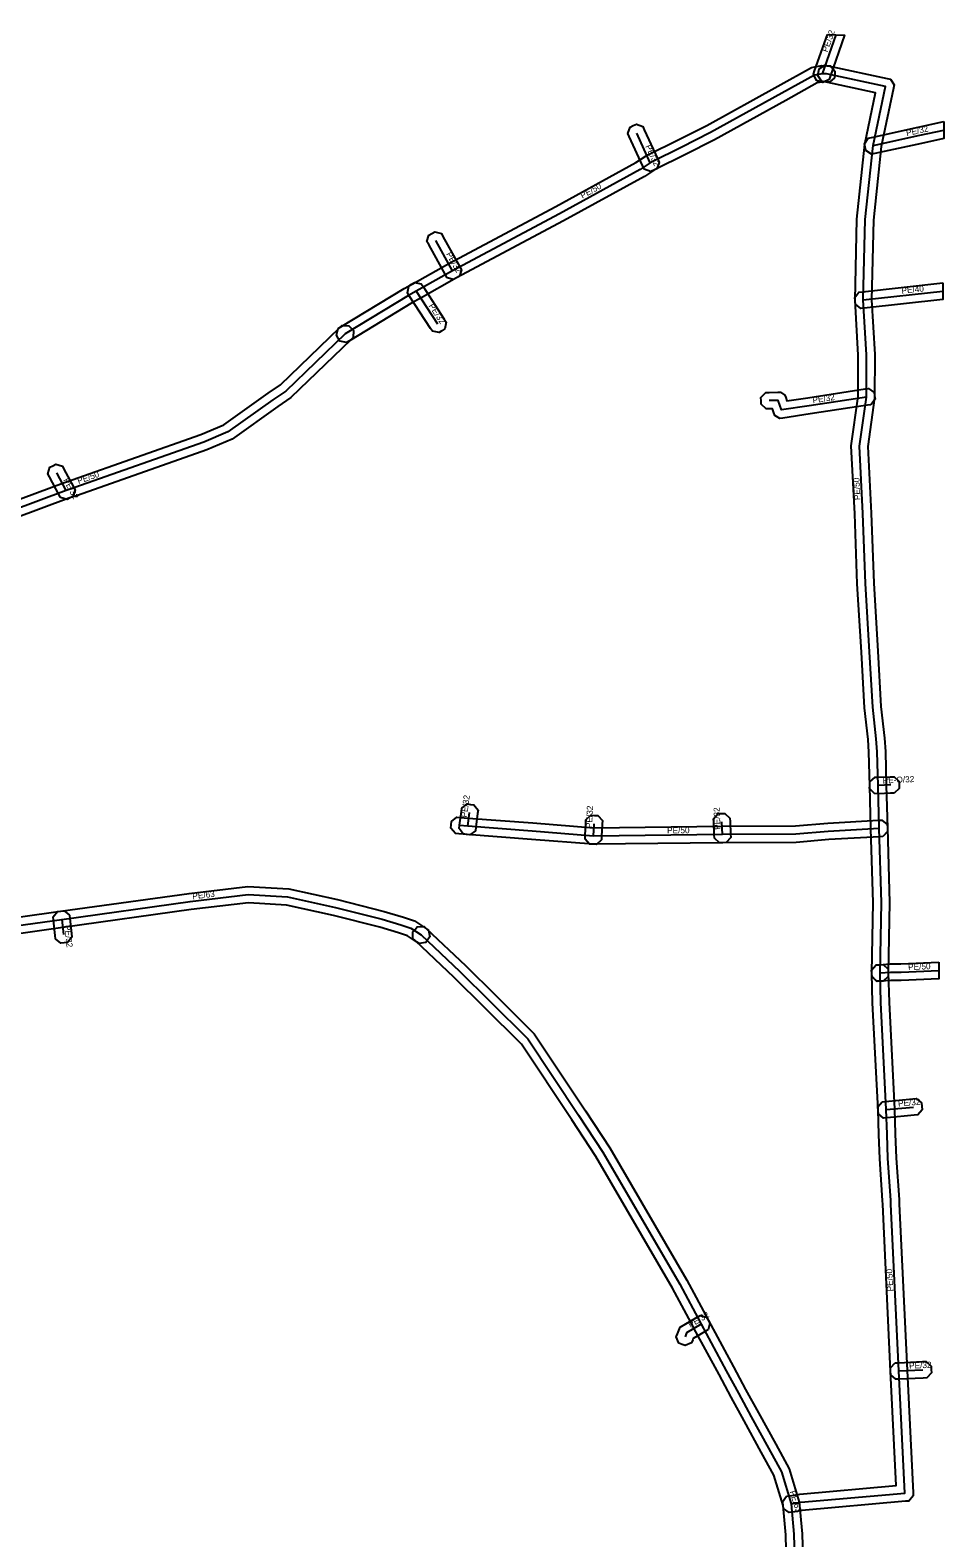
# Model space of a CAD drawing. Extents: x -682697 to -681888, y -1059966 to -1059631.
# Drawn here: x -681998.6 to -681887.6, y -1059827 to -1059643.6 of the extents above; entities that cross this region are included whole.
import ezdxf

# ---------------------------------------------------------------- set-up
doc = ezdxf.new("R2010")
doc.units = 0
for name, color, linetype in [('1', 7, 'Continuous'), ('24', 7, 'Continuous'), ('30', 7, 'Continuous')]:
    doc.layers.add(name, color=color, linetype=linetype)

msp = doc.modelspace()

# ---------------------------------------------------------------- linework, layer by layer
at = {"layer": '1'}
for points in [[(-681901.72, -1059644.16), (-681899.63, -1059644.25), (-681901.39, -1059649.25), (-681901.52, -1059649.64), (-681902.27, -1059650), (-681902.66, -1059649.86), (-681903.05, -1059649.73), (-681903.41, -1059648.98), (-681903.27, -1059648.59)], [(-681901.48, -1059649.97), (-681901.89, -1059649.95), (-681902.27, -1059649.93), (-681902.95, -1059650.05), (-681906.79, -1059652.17), (-681915.45, -1059656.97), (-681919.06, -1059658.79), (-681922.58, -1059660.53), (-681922.74, -1059660.61), (-681923.96, -1059661.44), (-681933.8, -1059666.83), (-681946.8, -1059673.76), (-681951.22, -1059676.24), (-681952.15, -1059676.76), (-681959.82, -1059681.42), (-681960.18, -1059681.63), (-681960.98, -1059681.43), (-681961.2, -1059681.08), (-681961.41, -1059680.72), (-681961.21, -1059679.92), (-681960.86, -1059679.71), (-681953.16, -1059675.04), (-681952.2, -1059674.5), (-681947.76, -1059672), (-681934.74, -1059665.07), (-681925, -1059659.74), (-681923.76, -1059658.89), (-681923.47, -1059658.74), (-681919.96, -1059657.01), (-681916.39, -1059655.21), (-681907.75, -1059650.42), (-681903.63, -1059648.15), (-681902.39, -1059647.91), (-681901.77, -1059647.95), (-681901.36, -1059647.98), (-681900.81, -1059648.6), (-681900.83, -1059649.01), (-681900.86, -1059649.42)], [(-681896.33, -1059758.67), (-681896.32, -1059758.26), (-681896.15, -1059749.72), (-681896.43, -1059740.74), (-681896.56, -1059735.51), (-681896.66, -1059731.44), (-681896.78, -1059729.9), (-681897.21, -1059726.04), (-681897.59, -1059719.28), (-681898.08, -1059710.97), (-681898.4, -1059702.43), (-681898.82, -1059694.19), (-681897.98, -1059688.18), (-681897.97, -1059683.15), (-681898.36, -1059676.45), (-681898.12, -1059666.6), (-681897.15, -1059657.49), (-681895.85, -1059651.24), (-681902.04, -1059649.93), (-681902.44, -1059649.84), (-681902.89, -1059649.15), (-681902.81, -1059648.74), (-681902.72, -1059648.34), (-681902.03, -1059647.89), (-681901.62, -1059647.97), (-681894.46, -1059649.49), (-681894.06, -1059649.58), (-681893.61, -1059650.27), (-681893.69, -1059650.67), (-681895.17, -1059657.79), (-681896.12, -1059666.74), (-681896.36, -1059676.41), (-681895.97, -1059683.09), (-681895.98, -1059688.32), (-681896.82, -1059694.27), (-681896.4, -1059702.35), (-681896.08, -1059710.87), (-681895.59, -1059719.16), (-681895.21, -1059725.88), (-681894.78, -1059729.72), (-681894.66, -1059731.34), (-681894.56, -1059735.46), (-681894.43, -1059740.68), (-681894.15, -1059749.7), (-681894.32, -1059758.3), (-681894.33, -1059758.71), (-681894.93, -1059759.29), (-681895.34, -1059759.28), (-681895.75, -1059759.27)], [(-681923.99, -1059660.54), (-681924.16, -1059660.17), (-681925.8, -1059656.56), (-681925.97, -1059656.19), (-681925.68, -1059655.41), (-681925.31, -1059655.24), (-681924.93, -1059655.07), (-681924.15, -1059655.36), (-681923.98, -1059655.74), (-681922.34, -1059659.33), (-681922.17, -1059659.71), (-681922.46, -1059660.49), (-681922.83, -1059660.66), (-681923.21, -1059660.83)], [(-681887.56, -1059654.74), (-681887.57, -1059656.79), (-681890.27, -1059657.39), (-681895.95, -1059658.62), (-681896.35, -1059658.71), (-681897.05, -1059658.26), (-681897.14, -1059657.85), (-681897.22, -1059657.45), (-681896.78, -1059656.75), (-681896.37, -1059656.66), (-681890.69, -1059655.43)], [(-681947.95, -1059673.73), (-681948.15, -1059673.37), (-681950.19, -1059669.71), (-681950.4, -1059669.34), (-681950.17, -1059668.55), (-681949.81, -1059668.35), (-681949.45, -1059668.15), (-681948.65, -1059668.37), (-681948.45, -1059668.73), (-681946.41, -1059672.39), (-681946.2, -1059672.76), (-681946.43, -1059673.55), (-681946.79, -1059673.75), (-681947.16, -1059673.96)], [(-681951.1, -1059674.48), (-681950.87, -1059674.82), (-681948.29, -1059678.79), (-681948.07, -1059679.14), (-681948.24, -1059679.95), (-681948.58, -1059680.18), (-681948.93, -1059680.4), (-681949.74, -1059680.23), (-681949.97, -1059679.89), (-681952.55, -1059675.92), (-681952.77, -1059675.57), (-681952.6, -1059674.76), (-681952.26, -1059674.53), (-681951.91, -1059674.31)], [(-681887.68, -1059674.36), (-681887.69, -1059676.37), (-681897.25, -1059677.42), (-681897.66, -1059677.47), (-681898.31, -1059676.95), (-681898.35, -1059676.54), (-681898.4, -1059676.13), (-681897.88, -1059675.48), (-681897.47, -1059675.44)], [(-681896.42, -1059689.18), (-681896.83, -1059689.24), (-681903.8, -1059690.3), (-681907.14, -1059690.8), (-681907.49, -1059690.85), (-681908.11, -1059690.49), (-681908.23, -1059690.15), (-681908.4, -1059689.67), (-681908.75, -1059689.68), (-681909.17, -1059689.69), (-681909.77, -1059689.12), (-681909.78, -1059688.71), (-681909.79, -1059688.29), (-681909.22, -1059687.69), (-681908.81, -1059687.68), (-681907.74, -1059687.65), (-681907.42, -1059687.64), (-681906.88, -1059688.01), (-681906.77, -1059688.31), (-681906.63, -1059688.7), (-681904.1, -1059688.32), (-681897.13, -1059687.26), (-681896.72, -1059687.2), (-681896.05, -1059687.69), (-681895.99, -1059688.1), (-681895.93, -1059688.51)], [(-681994.95, -1059700.46), (-681995.14, -1059700.09), (-681996.29, -1059697.94), (-681996.49, -1059697.58), (-681996.25, -1059696.78), (-681995.88, -1059696.59), (-681995.52, -1059696.39), (-681994.72, -1059696.63), (-681994.53, -1059697), (-681993.38, -1059699.15), (-681993.18, -1059699.51), (-681993.42, -1059700.31), (-681993.79, -1059700.5), (-681994.15, -1059700.7)], [(-681893.59, -1059736.42), (-681894, -1059736.42), (-681894.03, -1059736.42), (-681895.51, -1059736.49), (-681895.6, -1059736.49), (-681896.01, -1059736.47), (-681896.58, -1059735.86), (-681896.56, -1059735.45), (-681896.54, -1059735.03), (-681895.93, -1059734.47), (-681895.52, -1059734.49), (-681895.51, -1059734.49), (-681894.07, -1059734.42), (-681894, -1059734.42), (-681893.59, -1059734.42), (-681893, -1059735.01), (-681893, -1059735.42), (-681893, -1059735.83)], [(-681946.5, -1059740.72), (-681946.44, -1059740.31), (-681946.22, -1059738.65), (-681946.17, -1059738.24), (-681945.51, -1059737.73), (-681945.1, -1059737.79), (-681944.69, -1059737.84), (-681944.18, -1059738.5), (-681944.24, -1059738.91), (-681944.46, -1059740.57), (-681944.51, -1059740.98), (-681945.17, -1059741.49), (-681945.58, -1059741.43), (-681945.99, -1059741.38)], [(-681894.96, -1059741.68), (-681895.37, -1059741.71), (-681901.54, -1059742.07), (-681905.5, -1059742.4), (-681914.47, -1059742.44), (-681930.19, -1059742.63), (-681937.69, -1059742.04), (-681945.53, -1059741.44), (-681946.53, -1059741.36), (-681946.94, -1059741.32), (-681947.48, -1059740.69), (-681947.45, -1059740.28), (-681947.41, -1059739.87), (-681946.78, -1059739.33), (-681946.37, -1059739.36), (-681945.37, -1059739.44), (-681937.53, -1059740.04), (-681930.13, -1059740.63), (-681914.49, -1059740.44), (-681905.58, -1059740.4), (-681901.68, -1059740.07), (-681895.49, -1059739.71), (-681895.08, -1059739.69), (-681894.46, -1059740.24), (-681894.43, -1059740.65), (-681894.41, -1059741.06)], [(-681931.18, -1059742), (-681931.16, -1059741.58), (-681931.09, -1059740.08), (-681931.07, -1059739.67), (-681930.46, -1059739.11), (-681930.04, -1059739.13), (-681929.63, -1059739.15), (-681929.07, -1059739.76), (-681929.09, -1059740.18), (-681929.16, -1059741.68), (-681929.18, -1059742.09), (-681929.79, -1059742.65), (-681930.21, -1059742.63), (-681930.62, -1059742.61)], [(-681915.46, -1059741.89), (-681915.48, -1059741.48), (-681915.54, -1059739.93), (-681915.56, -1059739.52), (-681914.99, -1059738.91), (-681914.58, -1059738.89), (-681914.17, -1059738.88), (-681913.56, -1059739.44), (-681913.54, -1059739.85), (-681913.48, -1059741.4), (-681913.46, -1059741.81), (-681914.03, -1059742.42), (-681914.44, -1059742.44), (-681914.85, -1059742.46)], [(-681993.86, -1059751.25), (-681993.81, -1059751.66), (-681993.61, -1059753.5), (-681993.56, -1059753.91), (-681994.08, -1059754.56), (-681994.49, -1059754.6), (-681994.9, -1059754.65), (-681995.55, -1059754.13), (-681995.59, -1059753.72), (-681995.8, -1059751.88), (-681995.84, -1059751.47), (-681995.33, -1059750.82), (-681994.91, -1059750.78), (-681994.5, -1059750.73)], [(-681888.15, -1059756.99), (-681888.17, -1059758.99), (-681892.74, -1059759.19), (-681894.02, -1059759.19), (-681895.25, -1059759.28), (-681895.66, -1059759.31), (-681896.29, -1059758.76), (-681896.32, -1059758.35), (-681896.35, -1059757.94), (-681895.8, -1059757.31), (-681895.39, -1059757.28), (-681894.1, -1059757.19), (-681892.78, -1059757.19)], [(-681906.69, -1059821.93), (-681906.28, -1059821.86), (-681905.07, -1059821.67), (-681893.35, -1059820.63), (-681894.03, -1059806.73), (-681894.99, -1059786.44), (-681895.01, -1059785.96), (-681895.35, -1059780.9), (-681895.45, -1059777.92), (-681895.56, -1059774.94), (-681896.22, -1059761.93), (-681896.32, -1059758.31), (-681896.33, -1059757.89), (-681895.76, -1059757.29), (-681895.35, -1059757.28), (-681894.93, -1059757.27), (-681894.33, -1059757.84), (-681894.32, -1059758.25), (-681894.22, -1059761.85), (-681893.56, -1059774.86), (-681893.46, -1059777.85), (-681893.35, -1059780.8), (-681893.01, -1059785.84), (-681892.99, -1059786.35), (-681892.03, -1059806.63), (-681891.3, -1059821.49), (-681891.28, -1059821.89), (-681891.81, -1059822.5), (-681892.21, -1059822.54), (-681904.83, -1059823.65), (-681905.96, -1059823.84), (-681906.37, -1059823.9), (-681907.04, -1059823.42), (-681907.11, -1059823.01), (-681907.17, -1059822.6)], [(-681895.07, -1059773.94), (-681894.65, -1059773.9), (-681891.34, -1059773.59), (-681890.93, -1059773.55), (-681890.29, -1059774.08), (-681890.25, -1059774.5), (-681890.21, -1059774.91), (-681890.74, -1059775.55), (-681891.16, -1059775.59), (-681894.47, -1059775.9), (-681894.88, -1059775.94), (-681895.52, -1059775.41), (-681895.56, -1059774.99), (-681895.59, -1059774.58)], [(-681916.2, -1059801.67), (-681916.56, -1059801.87), (-681918.03, -1059802.73), (-681918.09, -1059802.89), (-681918.24, -1059803.27), (-681919, -1059803.6), (-681919.39, -1059803.45), (-681919.77, -1059803.3), (-681920.1, -1059802.54), (-681919.95, -1059802.15), (-681919.63, -1059801.35), (-681917.56, -1059800.15), (-681917.2, -1059799.94), (-681916.4, -1059800.15), (-681916.2, -1059800.51), (-681915.99, -1059800.86)], [(-681893.49, -1059805.7), (-681893.07, -1059805.68), (-681890.14, -1059805.55), (-681889.73, -1059805.53), (-681889.12, -1059806.09), (-681889.1, -1059806.51), (-681889.08, -1059806.92), (-681889.64, -1059807.53), (-681890.06, -1059807.55), (-681892.99, -1059807.68), (-681893.4, -1059807.7), (-681894.01, -1059807.14), (-681894.03, -1059806.72), (-681894.05, -1059806.31)]]:
    msp.add_lwpolyline(points, close=True, dxfattribs=at)
for points in [[(-682004.75, -1059702.45), (-681994.59, -1059698.68), (-681993.53, -1059698.31), (-681977.87, -1059692.8), (-681975.08, -1059691.61), (-681969.7, -1059687.77), (-681968.21, -1059686.74), (-681961.03, -1059679.84), (-681960.73, -1059679.55), (-681959.91, -1059679.57), (-681959.62, -1059679.87), (-681959.33, -1059680.17), (-681959.35, -1059680.99), (-681959.65, -1059681.28), (-681966.93, -1059688.28), (-681968.54, -1059689.41), (-681974.1, -1059693.37), (-681977.15, -1059694.66), (-681992.87, -1059700.21), (-681993.93, -1059700.56), (-682004.05, -1059704.33)], [(-682004.99, -1059752.18), (-681994.94, -1059750.78), (-681979.32, -1059748.6), (-681972.17, -1059747.75), (-681967.21, -1059748.05), (-681961.29, -1059749.36), (-681955.6, -1059750.79), (-681953.26, -1059751.49), (-681951.9, -1059751.94), (-681950.57, -1059752.83), (-681950.22, -1059753.06), (-681950.06, -1059753.87), (-681950.29, -1059754.21), (-681950.52, -1059754.56), (-681951.33, -1059754.72), (-681951.67, -1059754.49), (-681952.78, -1059753.76), (-681953.86, -1059753.39), (-681956.12, -1059752.73), (-681961.75, -1059751.3), (-681967.49, -1059750.03), (-681972.11, -1059749.75), (-681979.06, -1059750.58), (-681994.67, -1059752.76), (-682004.65, -1059754.16)], [(-681906.64, -1059832.17), (-681906.79, -1059826.6), (-681907.11, -1059823.04), (-681908.24, -1059819.35), (-681909.76, -1059816.55), (-681911.85, -1059812.75), (-681913.42, -1059809.88), (-681914.89, -1059807.12), (-681917.95, -1059801.47), (-681918, -1059801.37), (-681920.54, -1059796.61), (-681929.86, -1059780.6), (-681932.79, -1059776.13), (-681938.91, -1059766.95), (-681943.43, -1059762.46), (-681947.08, -1059758.82), (-681951.8, -1059754.39), (-681952.11, -1059754.11), (-681952.13, -1059753.28), (-681951.85, -1059752.98), (-681951.57, -1059752.67), (-681950.74, -1059752.65), (-681950.44, -1059752.93), (-681945.7, -1059757.38), (-681942.02, -1059761.04), (-681937.35, -1059765.67), (-681931.13, -1059775.03), (-681928.16, -1059779.54), (-681918.8, -1059795.63), (-681916.22, -1059800.45), (-681916.17, -1059800.55), (-681913.13, -1059806.18), (-681911.66, -1059808.92), (-681910.09, -1059811.79), (-681908, -1059815.59), (-681906.38, -1059818.57), (-681905.13, -1059822.66), (-681904.79, -1059826.48), (-681904.64, -1059832.15)]]:
    msp.add_lwpolyline(points, dxfattribs=at)
at = {"layer": '24'}
for points in [[(-681902.33, -1059648.92), (-681900.67, -1059644.2)], [(-681901.83, -1059648.95), (-681902.33, -1059648.92), (-681903.29, -1059649.1), (-681907.27, -1059651.29), (-681915.92, -1059656.09), (-681919.51, -1059657.9), (-681923.03, -1059659.64), (-681923.25, -1059659.75), (-681924.48, -1059660.59), (-681934.27, -1059665.95), (-681947.28, -1059672.88), (-681951.71, -1059675.37), (-681952.65, -1059675.9), (-681960.34, -1059680.56)], [(-681895.32, -1059758.28), (-681895.15, -1059749.71), (-681895.43, -1059740.71), (-681895.56, -1059735.49), (-681895.66, -1059731.39), (-681895.78, -1059729.81), (-681896.21, -1059725.96), (-681896.59, -1059719.22), (-681897.08, -1059710.92), (-681897.4, -1059702.39), (-681897.82, -1059694.23), (-681896.98, -1059688.25), (-681896.97, -1059683.12), (-681897.36, -1059676.43), (-681897.12, -1059666.67), (-681896.16, -1059657.64), (-681894.67, -1059650.47), (-681901.83, -1059648.95)], [(-681923.25, -1059659.75), (-681924.89, -1059656.15)], [(-681896.16, -1059657.64), (-681890.48, -1059656.41), (-681887.57, -1059655.77)], [(-681947.28, -1059672.88), (-681949.32, -1059669.22)], [(-681951.71, -1059675.37), (-681949.13, -1059679.34)], [(-681897.36, -1059676.43), (-681887.68, -1059675.37)], [(-681960.34, -1059680.56), (-681967.57, -1059687.51), (-681969.12, -1059688.59), (-681974.59, -1059692.49), (-681977.51, -1059693.73), (-681993.2, -1059699.26), (-681994.26, -1059699.62), (-682004.4, -1059703.39), (-682013.19, -1059706.71), (-682017.28, -1059708), (-682025.61, -1059714.34), (-682026.38, -1059714.76)], [(-681896.98, -1059688.25), (-681903.95, -1059689.31), (-681907.29, -1059689.81), (-681907.71, -1059688.65), (-681908.78, -1059688.68)], [(-681994.26, -1059699.62), (-681995.41, -1059697.47)], [(-681894, -1059735.42), (-681894.05, -1059735.42), (-681895.51, -1059735.49), (-681895.56, -1059735.49)], [(-681895.43, -1059740.71), (-681901.61, -1059741.07), (-681905.54, -1059741.4), (-681914.48, -1059741.44), (-681930.16, -1059741.63), (-681937.61, -1059741.04), (-681945.45, -1059740.44), (-681946.45, -1059740.36)], [(-681945.45, -1059740.44), (-681945.23, -1059738.78)], [(-681930.16, -1059741.63), (-681930.09, -1059740.13)], [(-681914.48, -1059741.44), (-681914.54, -1059739.89)], [(-682006.81, -1059753.58), (-682004.82, -1059753.17), (-681994.8, -1059751.77), (-681979.19, -1059749.59), (-681972.14, -1059748.75), (-681967.35, -1059749.04), (-681961.52, -1059750.33), (-681955.86, -1059751.76), (-681953.56, -1059752.44), (-681952.34, -1059752.85), (-681951.12, -1059753.66)], [(-681994.8, -1059751.77), (-681994.6, -1059753.61)], [(-681951.12, -1059753.66), (-681946.39, -1059758.1), (-681942.72, -1059761.75), (-681938.13, -1059766.31), (-681931.96, -1059775.58), (-681929.01, -1059780.07), (-681919.67, -1059796.12), (-681917.11, -1059800.91), (-681917.06, -1059801.01), (-681914.01, -1059806.65), (-681912.54, -1059809.4), (-681910.97, -1059812.27), (-681908.88, -1059816.07), (-681907.31, -1059818.96), (-681906.12, -1059822.85), (-681905.79, -1059826.54), (-681905.64, -1059832.16), (-681905.69, -1059849.74), (-681907.73, -1059860.38), (-681911.27, -1059877.23), (-681913.72, -1059886.35), (-681915.15, -1059891.51), (-681917.44, -1059900.24), (-681918, -1059901.81)], [(-681906.12, -1059822.85), (-681904.95, -1059822.66), (-681892.3, -1059821.54), (-681893.03, -1059806.68), (-681893.99, -1059786.39), (-681894.01, -1059785.9), (-681894.35, -1059780.85), (-681894.45, -1059777.89), (-681894.56, -1059774.9), (-681895.22, -1059761.89), (-681895.32, -1059758.28)], [(-681895.32, -1059758.28), (-681894.06, -1059758.19), (-681892.76, -1059758.19), (-681888.16, -1059757.99)], [(-681894.56, -1059774.9), (-681891.25, -1059774.59)], [(-681917.06, -1059801.01), (-681918.83, -1059802.04), (-681919.02, -1059802.52)], [(-681893.03, -1059806.68), (-681890.1, -1059806.55)]]:
    msp.add_lwpolyline(points, dxfattribs=at)

# ---------------------------------------------------------------- texts
at = {"layer": '30'}
for s, rotation, p in [('PE/32', 70.6574, (-681901.7, -1059646.36)), ('PE/32', 12.2187, (-681892.06, -1059656.51)), ('PE/32', 294.4919, (-681923.87, -1059657.75)), ('PE/50', 28.7006, (-681931.5, -1059664.13)), ('PE/32', 299.1343, (-681948.1, -1059670.85)), ('PE/40', 6.2778, (-681892.67, -1059675.69)), ('PE/32', 303.0188, (-681950.22, -1059677.16)), ('PE/32', 8.6473, (-681903.47, -1059689.01)), ('PE/32', 298.1416, (-681994.64, -1059698.34)), ('PE/50', 19.4152, (-681992.75, -1059698.83)), ('PE/50', 92.9464, (-681897.69, -1059700.76)), ('PE-O/32', 2.745, (-681894.98, -1059735.25)), ('PE/32', 82.4506, (-681945.54, -1059739.41)), ('PE/32', 87.3281, (-681930.33, -1059740.68)), ('PE/32', 92.2168, (-681914.71, -1059740.86)), ('PE/50', 0.6942, (-681921.2, -1059741.32)), ('PE/63', 6.7947, (-681978.87, -1059749.33)), ('PE/32', 276.3265, (-681994.5, -1059752.49)), ('PE/50', 2.4612, (-681891.89, -1059757.94)), ('PE/32', 5.3505, (-681893.1, -1059774.55)), ('PE/50', 92.7008, (-681893.7, -1059796.99)), ('PE/32', 30.196, (-681918.37, -1059801.45)), ('PE/32', 2.5405, (-681891.77, -1059806.42)), ('PE/63', 287.0095, (-681906.32, -1059821.36))]:
    msp.add_text(s, height=0.75, rotation=rotation, dxfattribs=at).set_placement(p)

doc.saveas('drawing.dxf')
